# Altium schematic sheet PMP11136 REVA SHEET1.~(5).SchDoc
size 431 x 279 mm; Date: Not shown in title block; ApprovedBy: Not shown in title block; CheckedBy: Not shown in title block; Author: Not shown in title block; CompanyName: Not shown in title block; Engineer: Not shown in title block; Organization: Not shown in title block; Address1: Not shown in title block; Address2: Not shown in title block; Address3: Not shown in title block; Address4: Not shown in title block; DocumentNumber: 1; Revision: Use project parameter SCH_Rev; SheetNumber: 1; SheetTotal: 3; PageSetup: Record=PageOptions¦CenterHorizontal=True¦CenterVertical=True¦PrintScale=1.00¦XCorrection=1.00¦YCorrection=1.00¦PrintKind=0¦BorderSize=5000000¦LeftOffset=0¦BottomOffset=0¦Orientation=2¦PaperLength=1000¦PaperWidth=1000¦Scale=100¦PaperSource=15¦PrintQuality=600¦MediaType=1¦DitherType=10¦PaperKind=Letter¦PrintScaleMode=1
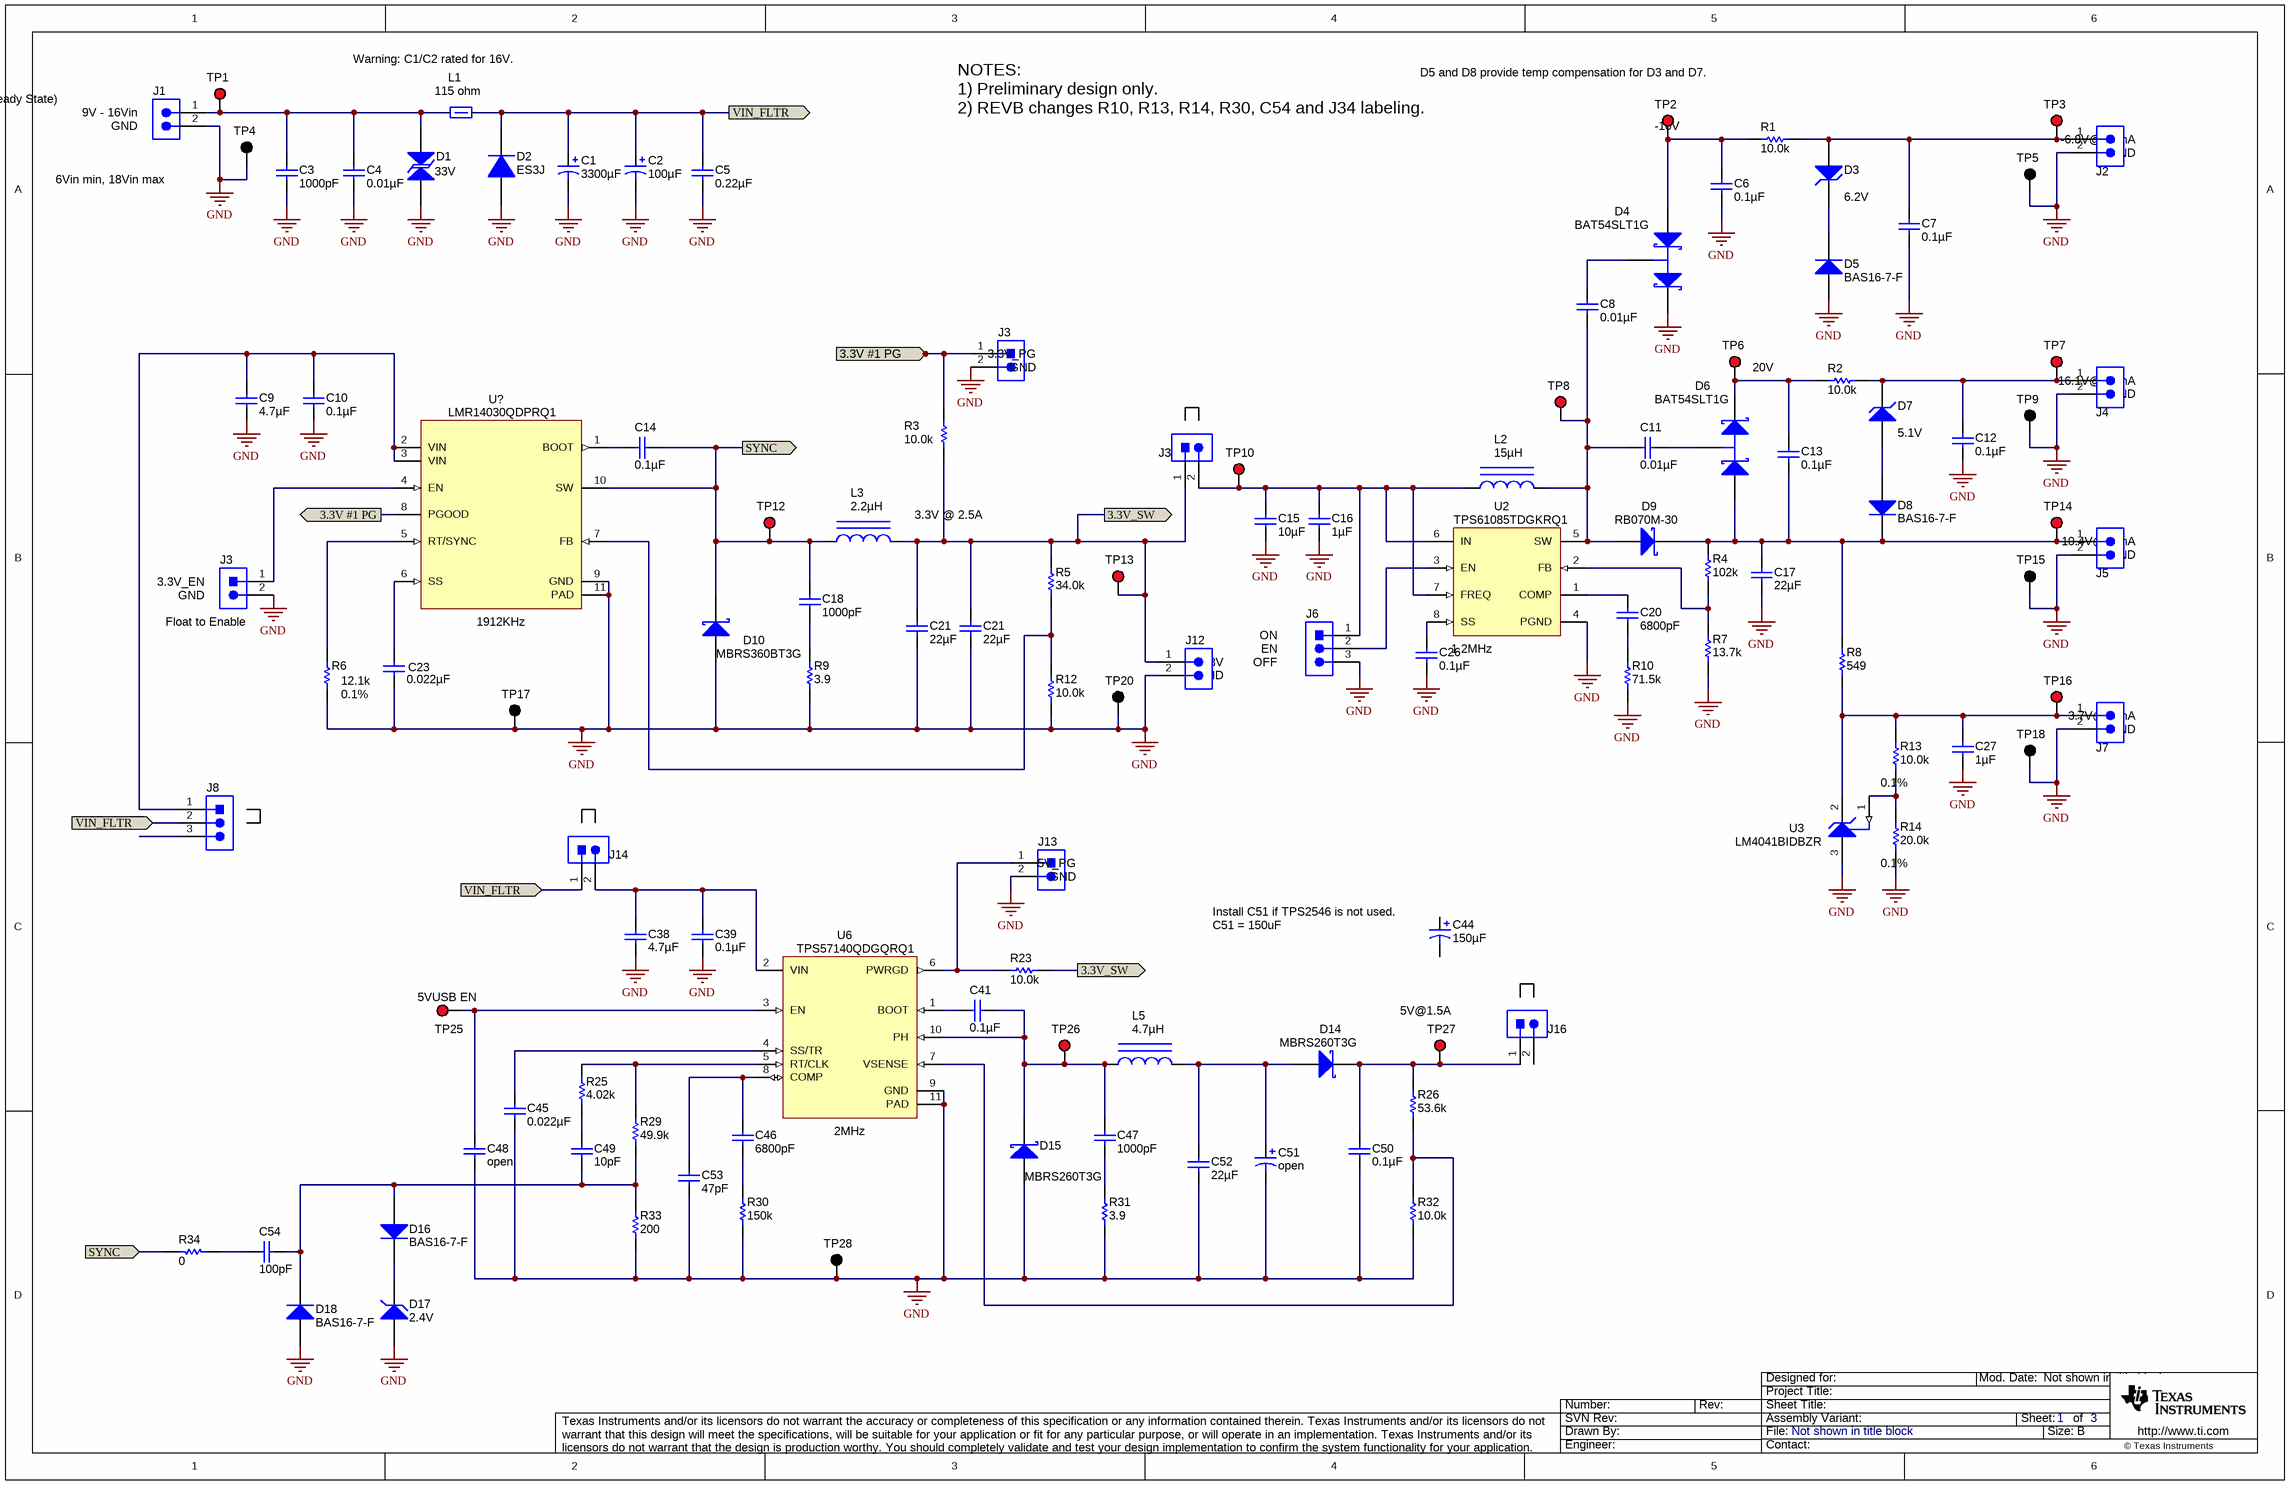
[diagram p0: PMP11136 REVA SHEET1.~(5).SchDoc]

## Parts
(Parts that share a designator on the sheet are numbered #1, #2 ... from top to bottom, then left to right.)
C1  ValueDisplayed: 3300µF  [SM_RADIAL_J16]  (hidden comment: EEV-FK1C332M)
C2  ValueDisplayed: 100µF  [SM_RADIAL_D]  (hidden comment: EEE-FK1C101P)
C3  ValueDisplayed: 1000pF  [0603]  (hidden comment: C1608C0G2A102J)
C4  ValueDisplayed: 0.01µF  [0603]  (hidden comment: C1608X7R2A103K)
C5  ValueDisplayed: 0.22µF  [0603]  (hidden comment: C1608X7R1H224K080AB)
C6  ValueDisplayed: 0.1µF  [0603]  (hidden comment: C1608X7R1H104K)
C7  ValueDisplayed: 0.1µF  [0603]  (hidden comment: C1608X7R1H104K)
C8  ValueDisplayed: 0.01µF  [0603]  (hidden comment: C1608X7R1H103K)
C9  ValueDisplayed: 4.7µF  [1210]  (hidden comment: C3225X7R1H475M250AB)
C10  ValueDisplayed: 0.1µF  [0603]  (hidden comment: C1608X7R1H104K)
C11  ValueDisplayed: 0.01µF  [0603]  (hidden comment: C1608X7R1H103K)
C12  ValueDisplayed: 0.1µF  [0603]  (hidden comment: C1608X7R1H104K)
C13  ValueDisplayed: 0.1µF  [0603]  (hidden comment: C1608X7R1H104K)
C14  ValueDisplayed: 0.1µF  [0603]  (hidden comment: C1608X7R1H104K)
C15  ValueDisplayed: 10µF  [0805]  (hidden comment: GRM21BR71A106KE51L)
C16  ValueDisplayed: 1µF  [0603]  (hidden comment: C1608X7R1E105K)
C17  ValueDisplayed: 22µF  [1210]  (hidden comment: C3225X7R1A226M230AC)
C18  ValueDisplayed: 1000pF  [0603]  (hidden comment: C1608C0G2A102J)
C20  ValueDisplayed: 6800pF  [0603]  (hidden comment: C1608C0G1E682J)
C21#1  ValueDisplayed: 22µF  [1210]  (hidden comment: C3225X7R1C226M250AC)
C21#2  ValueDisplayed: 22µF  [1210]  (hidden comment: C3225X7R1C226M250AC)
C23  ValueDisplayed: 0.022µF  [0603]  (hidden comment: C1608X7R1H223K)
C26  ValueDisplayed: 0.1µF  [0603]  (hidden comment: C1608X7R1H104K)
C27  ValueDisplayed: 1µF  [0603]  (hidden comment: C1608X7R1E105K)
C38  ValueDisplayed: 4.7µF  [1210]  (hidden comment: C3225X7R1H475M250AB)
C39  ValueDisplayed: 0.1µF  [0603]  (hidden comment: C1608X7R1H104K)
C41  ValueDisplayed: 0.1µF  [0603]  (hidden comment: C1608X7R1H104K)
C44  ValueDisplayed: 150µF  [TPB_D4]  (hidden comment: 10TPB150ML)
C45  ValueDisplayed: 0.022µF  [0603]  (hidden comment: C1608X7R1H223K)
C46  ValueDisplayed: 6800pF  [0603]  (hidden comment: C1608C0G1E682J)
C47  ValueDisplayed: 1000pF  [0603]  (hidden comment: C1608C0G2A102J)
C48  ValueDisplayed: open  [0603]
C49  ValueDisplayed: 10pF  [0603]  (hidden comment: C1608C0G1H100D)
C50  ValueDisplayed: 0.1µF  [0603]  (hidden comment: C1608X7R1H104K)
C51  ValueDisplayed: open  [TPB_D4]
C52  ValueDisplayed: 22µF  [1210]  (hidden comment: C3225X7R1A226M230AC)
C53  ValueDisplayed: 47pF  [0603]  (hidden comment: C1608C0G1H470J)
C54  ValueDisplayed: 100pF  [0603]  (hidden comment: C1608C0G1H101J)
D1  value 33V  [DO-214AB-Bi]  (hidden comment: 1.5SMC33CA-E3/57T)
D2  ES3J  [SMC]
D3  value 6.2V  [SOD-123]  (hidden comment: MMSZ5234B-7-F)
D4  BAT54SLT1G  [SOT-23]
D5  BAS16-7-F  [SOT-23]
D6  BAT54SLT1G  [SOT-23]
D7  value 5.1V  [SOD-123]  (hidden comment: MMSZ5231B-7-F)
D8  BAS16-7-F  [SOT-23]
D9  RB070M-30  [SOD-123]
D10  MBRS360BT3G  [SMB]
D14  MBRS260T3G  [SMB]
D15  MBRS260T3G  [SMB]
D16  BAS16-7-F  [SOT-23]
D17  value 2.4V  [SOD-123]  (hidden comment: MMSZ5221B-7-F)
D18  BAS16-7-F  [SOT-23]
J1  ED555/2DS  [TERM_BLK_ED555-2DS]  (value not drawn)
J2  ED555/2DS  [TERM_BLK_ED555-2DS]  (value not drawn)
J3#1  PEC02SAAN  [CONN_PEC02SAAN]  (value not drawn)
J3#2  PEC02SAAN  [CONN_PEC02SAAN]  (value not drawn)
J3#3  PEC02SAAN  [CONN_PEC02SAAN]  (value not drawn)
J4  ED555/2DS  [TERM_BLK_ED555-2DS]  (value not drawn)
J5  ED555/2DS  [TERM_BLK_ED555-2DS]  (value not drawn)
J6  PEC03SAAN  [CONN_PEC03SAAN]  (value not drawn)
J7  ED555/2DS  [TERM_BLK_ED555-2DS]  (value not drawn)
J8  PEC03SAAN  [CONN_PEC03SAAN]  (value not drawn)
J12  ED555/2DS  [TERM_BLK_ED555-2DS]  (value not drawn)
J13  PEC02SAAN  [CONN_PEC02SAAN]  (value not drawn)
J14  PEC02SAAN  [CONN_PEC02SAAN]  (value not drawn)
J16  PEC02SAAN  [CONN_PEC02SAAN]  (value not drawn)
L1  value 115 ohm  [28F0181]  (hidden comment: 28F0181-1SR-10)
L2  ValueDisplayed: 15µH  [IND_VLF403215]  (hidden comment: VLF403215MT- 150M)
L3  ValueDisplayed: 2.2µH  [SDR7045]  (hidden comment: SLF6045T-2R2N3R3-3PF)
L5  ValueDisplayed: 4.7µH  [SDR7045]  (hidden comment: SLF6045T-4R7N2R4-3PF)
R1  ValueDisplayed: 10.0k  [0603]  (hidden comment: CRCW060310K0FKEA)
R2  ValueDisplayed: 10.0k  [0603]  (hidden comment: CRCW060310K0FKEA)
R3  ValueDisplayed: 10.0k  [0603]  (hidden comment: CRCW060310K0FKEA)
R4  ValueDisplayed: 102k  [0603]  (hidden comment: CRCW0603102KFKEA)
R5  ValueDisplayed: 34.0k  [0603]  (hidden comment: CRCW060334K0FKEA)
R6  Value1: 0.1%  ValueDisplayed: 12.1k  [0603]
R7  ValueDisplayed: 13.7k  [0603]  (hidden comment: CRCW060313K7FKEA)
R8  value 549  [0805_HV]  (hidden comment: CRCW0805549RFKEA)
R9  value 3.9  [2010]  (hidden comment: CRCW20103R90JNEF)
R10  ValueDisplayed: 71.5k  [0603]  (hidden comment: CRCW060371K5FKEA)
R12  ValueDisplayed: 10.0k  [0603]  (hidden comment: CRCW060310K0FKEA)
R13  ValueDisplayed: 10.0k  [0603]  (hidden comment: CRCW060310K0FKEA)
R14  ValueDisplayed: 20.0k  [0603]  (hidden comment: CRCW0603210K0FKEA)
R23  ValueDisplayed: 10.0k  [0603]  (hidden comment: CRCW060310K0FKEA)
R25  ValueDisplayed: 4.02k  [0603]  (hidden comment: CRCW06034K02FKEA)
R26  ValueDisplayed: 53.6k  [0603]  (hidden comment: CRCW060353K6FKEA)
R29  ValueDisplayed: 49.9k  [0603]  (hidden comment: CRCW060349K9FKEA)
R30  ValueDisplayed: 150k  [0603]  (hidden comment: CRCW0603150KFKEA)
R31  value 3.9  [2010]  (hidden comment: CRCW20103R90JNEF)
R32  ValueDisplayed: 10.0k  [0603]  (hidden comment: CRCW060310K0FKEA)
R33  ValueDisplayed: 200  [0603]  (hidden comment: CRCW0603200RFKEA)
R34  ValueDisplayed: 0  [0603]  (hidden comment: CRCW06030000Z0EA)
TP1  5000  [Keystone5000]  (value not drawn)
TP2  5000  [Keystone5000]  (value not drawn)
TP3  5000  [Keystone5000]  (value not drawn)
TP4  5001  [Keystone5001]  (value not drawn)
TP5  5001  [Keystone5001]  (value not drawn)
TP6  5000  [Keystone5000]  (value not drawn)
TP7  5000  [Keystone5000]  (value not drawn)
TP8  5000  [Keystone5000]  (value not drawn)
TP9  5001  [Keystone5001]  (value not drawn)
TP10  5000  [Keystone5000]  (value not drawn)
TP12  5000  [Keystone5000]  (value not drawn)
TP13  5000  [Keystone5000]  (value not drawn)
TP14  5000  [Keystone5000]  (value not drawn)
TP15  5001  [Keystone5001]  (value not drawn)
TP16  5000  [Keystone5000]  (value not drawn)
TP17  5001  [Keystone5001]  (value not drawn)
TP18  5001  [Keystone5001]  (value not drawn)
TP20  5001  [Keystone5001]  (value not drawn)
TP25  5000  [Keystone5000]  (value not drawn)
TP26  5000  [Keystone5000]  (value not drawn)
TP27  5000  [Keystone5000]  (value not drawn)
TP28  5001  [Keystone5001]  (value not drawn)
U2  TPS61085TDGKRQ1  [DGK0008A_N]
U3  LM4041BIDBZR  [DBZ0003A_N]
U6  TPS57140QDGQRQ1  [DGQ0010D_N]
U?  LMR14030QDPRQ1  [DPR0010A]

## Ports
3.3V #1 PG, 3.3V_SW, SYNC, VIN_FLTR

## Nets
GND: C1.2(-) C2.2(-) C3.2 C4.2 C5.2 C6.2 C7.2 C9.1 C10.2 C12.2 C15.2 C16.2 C17.2 C21#1.2 C21#2.2 C23.2 C26.2 C27.2 C38.1 C39.2 C45.2 C48.2 C50.2 C51.2(-) C52.2 C53.2 D1.1 D2.2(A) D4.2(K) D5.1(A) D10.2(A) D15.2(A) D17.2(A) D18.1(A) J1.2 J2.2 J3#1.2 J3#3.2 J4.2 J5.2 J6.3 J7.2 J12.2 J13.2 R6.1 R7.1 R9.1 R10.1 R12.1 R14.1 R30.1 R31.1 R32.1 R33.1 TP4.1 TP5.1 TP9.1 TP15.1 TP17.1 TP18.1 TP20.1 TP28.1 U2.4(PGND) U3.3(ANODE) U6.9(GND) U6.11(PAD) U?.9(GND) U?.11(PAD)
3.3V #1 PG: J3#1.1 R3.2 U?.8(PGOOD) ; port 3.3V #1 PG
3.3V_SW: C21#1.1 C21#2.1 J3#2.1 J12.1 L3.2 R3.1 R5.2 R23.1 TP13.1 ; port 3.3V_SW
SYNC: C14.2 C18.1 D10.1(K) L3.1 R34.1 TP12.1 U?.10(SW) ; port SYNC
VIN_FLTR: C1.1(+) C2.1(+) C5.1 D2.1(K) J8.2 J14.1 L1.2 ; port VIN_FLTR
NetC3_1: C3.1 C4.1 D1.2 J1.1 L1.1 TP1.1
NetC6_1: C6.1 D4.1(A) R1.2 TP2.1
NetC7_1: C7.1 D3.2(A) J2.1 R1.1 TP3.1
NetC8_1: C8.1 C11.1 D9.2(A) L2.2 TP8.1 U2.5(SW)
NetC8_2: C8.2 D4.3(C)
NetC9_2: C9.2 C10.1 J8.1 U?.2(VIN) U?.3(VIN)
NetC11_2: C11.2 D6.3(C)
NetC12_1: C12.1 D7.1(K) J4.1 R2.1 TP7.1
NetC13_1: C13.1 D6.2(K) R2.2 TP6.1
NetC13_2: C13.2 C17.1 D6.1(A) D8.3(K) D9.1(K) J5.1 R4.2 R8.2 TP14.1
NetC14_1: C14.1 U?.1(BOOT)
NetC15_1: C15.1 C16.1 J3#2.2 J6.1 L2.1 TP10.1 U2.6(IN) U2.7(FREQ)
NetC18_2: C18.2 R9.2
NetC20_1: C20.1 U2.1(COMP)
NetC20_2: C20.2 R10.2
NetC23_1: C23.1 U?.6(SS)
NetC26_1: C26.1 U2.8(SS)
NetC27_1: C27.1 J7.1 R8.1 R13.2 TP16.1 U3.2(CATHODE)
NetC38_2: C38.2 C39.1 J14.2 U6.2(VIN)
NetC41_1: C41.1 U6.1(BOOT)
NetC41_2: C41.2 C47.1 D15.1(K) L5.1 TP26.1 U6.10(PH)
NetC45_1: C45.1 U6.4(SS/TR)
NetC46_1: C46.1 C53.1 U6.8(COMP)
NetC46_2: C46.2 R30.2
NetC47_2: C47.2 R31.2
NetC48_1: C48.1 TP25.1 U6.3(EN)
NetC49_1: C49.1 R25.2
NetC49_2: C49.2 C54.1 D16.1(A) D18.3(K) R29.1 R33.2
NetC50_1: C50.1 D14.1(K) J16.1 R26.2 TP27.1
NetC51_1: C51.1(+) C52.1 D14.2(A) L5.2
NetC54_2: C54.2 R34.2
NetD3_1: D3.1(K) D5.3(K)
NetD7_2: D7.2(A) D8.1(A)
NetD16_3: D16.3(K) D17.1(K)
NetJ3#3_1: J3#3.1 U?.4(EN)
NetJ6_2: J6.2 U2.3(EN)
NetJ13_1: J13.1 R23.2 U6.6(PWRGD)
NetR4_1: R4.1 R7.2 U2.2(FB)
NetR5_1: R5.1 R12.2 U?.7(FB)
NetR6_2: R6.2 U?.5(RT/SYNC)
NetR13_1: R13.1 R14.2 U3.1(FB)
NetR25_1: R25.1 R29.2 U6.5(RT/CLK)
NetR26_1: R26.1 R32.2 U6.7(VSENSE)

Not connected (* = marked no-connect by the designer): C44 1(+) 2(-); J8 3; J16 2

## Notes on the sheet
- (near J1) (Steady State)
- Warning: C1/C2 rated for 16V.
- D5 and D8 provide temp compensation for D3 and D7.
- (near J1) 9V - 16Vin
- (near J1) GND
- NOTES:
  1) Preliminary design only.
  2) REVB changes R10, R13, R14, R30, C54 and J34 labeling.
- (near TP2) -10V
- (near J2) -6.8V@0.3mA
- (near J2) GND
- (near J1) 6Vin min, 18Vin max
- (near J3#1) 3.3V_PG
- (near J3#1) GND
- 20V
- (near J4) 16.1V@0.3mA
- (near J4) GND
- 3.3V @ 2.5A
- (near J5) 10.4V@30mA
- (near J5) GND
- (near J3#3) 3.3V_EN
- (near J3#3) GND
- (near J3#3) Float to Enable
- (near U?) 1912KHz
- (near J6) ON
- (near J12) 3.3V
- (near J12) GND
- (near J6) EN
- (near J6) OFF
- (near U2) 1.2MHz
- (near J7) 3.7V@10mA
- (near J7) GND
- (near R13) 0.1%
- (near J13) 5V_PG
- (near J13) GND
- (near R14) 0.1%
- (near C44) Install C51 if TPS2546 is not used.
  C51 = 150uF
- (near TP25) 5VUSB EN
- (near TP27) 5V@1.5A
- (near U6) 2MHz

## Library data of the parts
C1 = EEV-FK1C332M: CAP, AL, 3300 µF, 16 V, +/- 20%, 0.035 ohm, SMD; Manufacturer: Panasonic; Polarized: Y; CompType: Capacitor; Value: 3300uF; U/M: EA; Cap_F: 0.0033; Tolerance_%: 20; VDC_V: 16; Value2: 16V; ESR_ohm: 0.035; IRMS_A: 1.8; TaMin_C: -55; TaMax_C: 105; Cap_Case: J16
C2 = EEE-FK1C101P: CAP, AL, 100 µF, 16 V, +/- 20%, 0.36 ohm, SMD; Manufacturer: Panasonic; Polarized: Y; CompType: Capacitor; Value: 100uF; U/M: EA; Cap_F: 0.0001; Tolerance_%: 20; VDC_V: 16; Value2: 16V; ESR_ohm: 0.36; IRMS_A: 0.24; TaMin_C: -55; TaMax_C: 105; Cap_Case: D
C3 C18 C47 = C1608C0G2A102J: CAP, CERM, 1000 pF, 100 V, +/- 5%, C0G/NP0, 0603; Manufacturer: TDK; Polarized: N; CompType: Capacitor; Value: 1000pF; U/M: EA; Cap_F: 0.000000001; Tolerance_%: 5; ESR_ohm: 0.0589; Value1: 0.0589 ohm; VDC_V: 100; Value2: 100V; TaMin_C: -55; TaMax_C: 125
C4 = C1608X7R2A103K: CAP, CERM, 0.01 µF, 100 V, +/- 10%, X7R, 0603; Manufacturer: TDK; Polarized: N; CompType: Capacitor; Value: 0.01uF; U/M: EA; Cap_F: 0.00000001; Tolerance_%: 10; ESR_ohm: 0.0661; Value1: 0.0661 ohm; VDC_V: 100; Value2: 100V; TaMin_C: -55; TaMax_C: 125
C5 = C1608X7R1H224K080AB: CAP, CERM, 0.22 µF, 50 V, +/- 10%, X7R, 0603; Manufacturer: TDK; Polarized: N; CompType: Capacitor; Value: 0.22uF; U/M: EA; Cap_F: 0.00000022; Tolerance_%: 10; Value1: Unknown; VDC_V: 50; Value2: 50V; TaMin_C: -55; TaMax_C: 125
C6 C7 C10 C12-C14 C26 C39 C41 C50 = C1608X7R1H104K: CAP, CERM, 0.1uF, 50V, +/-10%, X7R, 0603; Manufacturer: TDK; Polarized: N; CompType: Capacitor; U/M: EA; Cap_F: 0.0000001; Tolerance_%: 10; ESR_Ohm: 0.017; Value1: 0.017 ohm; VDC_V: 50; TaMin_C: -55; TaMax_C: 125
C8 C11 = C1608X7R1H103K: CAP, CERM, 0.01 µF, 50 V, +/- 10%, X7R, 0603; Manufacturer: TDK; Polarized: N; CompType: Capacitor; Value: 0.01uF; U/M: EA; Cap_F: 0.00000001; Tolerance_%: 10; ESR_ohm: 0.0539; Value1: 0.0539 ohm; VDC_V: 50; Value2: 50V; TaMin_C: -55; TaMax_C: 125
C9 C38 = C3225X7R1E106M: CAP, CERM, 4.7uF, 50V, +/-20%, X7R, 1210; Manufacturer: TDK; Polarized: N; CompType: Capacitor; U/M: EA; Cap_F: 0.00001; Tolerance_%: 20; ESR_Ohm: 0.0027; Value1: 0.0027 ohm; VDC_V: 50; IRMS_A: 3; TaMin_C: -55; TaMax_C: 125
C15 = GRM21BR71A106KE51L: CAP, CERM, 10uF, 10V, +/-10%, X7R, 0805; Manufacturer: MuRata; Polarized: N; CompType: Capacitor; U/M: EA; Cap_F: 0.00001; Tolerance_%: 10; ESR_Ohm: 0.003; Value1: 0.003 ohm; TaMin_C: -55; TaMax_C: 125
C16 C27 = C1608X7R1C105K: CAP, CERM, 1uF, 25V, +/-10%, X7R, 0603; Manufacturer: TDK; Polarized: N; CompType: Capacitor; U/M: EA; Cap_F: 0.000001; Tolerance_%: 10; ESR_Ohm: 0.0057; Value1: 0.0057 ohm; VDC_V: 25; TaMin_C: -55; TaMax_C: 125
C17 C21#1 C21#2 C52 = C3225X7R1C226M: CAP, CERM, 22 µF, 16 V, +/- 20%, X7R, 1210; Manufacturer: TDK; Polarized: N; CompType: Capacitor; Value: 22uF; U/M: EA; Cap_F: 0.000022; Tolerance_%: 20; ESR_ohm: 0.002; Value1: 0.002 ohm; VDC_V: 16; Value2: 16V; IRMS_A: 8.11; TaMin_C: -55; TaMax_C: 125
C20 C46 = C1608C0G1E682J: CAP, CERM, 6800 pF, 25 V, +/- 5%, C0G/NP0, 0603; Manufacturer: TDK; Polarized: N; CompType: Capacitor; Value: 6800pF; U/M: EA; Cap_F: 0.0000000068; Tolerance_%: 5; Value1: Unknown; VDC_V: 25; Value2: 25V; TaMin_C: -55; TaMax_C: 125
C23 C45 = C1608X7R1H223K: CAP, CERM, 0.022 µF, 50 V, +/- 10%, X7R, 0603; Manufacturer: TDK; Polarized: N; CompType: Capacitor; Value: 0.022uF; U/M: EA; Cap_F: 0.000000022; Tolerance_%: 10; ESR_ohm: 0.0383; Value1: 0.0383 ohm; VDC_V: 50; Value2: 50V; TaMin_C: -55; TaMax_C: 125
C44 = 10TPB220M: CAP, 150uF, 10V, +/-20%, 0.04 ohm, SMD; Manufacturer: Panasonic; Polarized: Y; CompType: Capacitor; U/M: EA; Cap_F: 0.00022; Tolerance_%: 20; VDC_V: 10; ESR_Ohm: 0.04; IRMS_A: 3; TaMin_C: -55; TaMax_C: 105; Cap_Case: D
C48 = C1608C0G1H102J: CAP, CERM, open, 0603; Polarized: N; CompType: Capacitor; U/M: EA; Cap_F: 0.000000001; Tolerance_%: 5; ESR_ohm: 0.0563; TempCo: C0G/NP0; TaMin_C: -55; TaMax_C: 125
C49 = C1608C0G1H100D: CAP, CERM, 10 pF, 50 V, +/- 5%, C0G/NP0, 0603; Manufacturer: TDK; Polarized: N; CompType: Capacitor; Value: 10pF; U/M: EA; Cap_F: 0.00000000001; Tolerance_%: 5; ESR_ohm: 0.3492; Value1: 0.3492 ohm; VDC_V: 50; Value2: 50V; TaMin_C: -55; TaMax_C: 125
C51 = 10TPB220M: CAP, open, SMD; Polarized: Y; CompType: Capacitor; U/M: EA; Cap_F: 0.00022; Tolerance_%: 20; ESR_Ohm: 0.04; IRMS_A: 3; TaMin_C: -55; TaMax_C: 105; Cap_Case: D
C53 = C1608C0G1H470J: CAP, CERM, 47 pF, 50 V, +/- 5%, C0G/NP0, 0603; Manufacturer: TDK; Polarized: N; CompType: Capacitor; Value: 47pF; U/M: EA; Cap_F: 0.000000000047; Tolerance_%: 5; ESR_ohm: 0.22; Value1: 0.22 ohm; VDC_V: 50; Value2: 50V; TaMin_C: -55; TaMax_C: 125
C54 = C1608C0G1H101J: CAP, CERM, 100 pF, 50 V, +/- 5%, C0G/NP0, 0603; Manufacturer: TDK; Polarized: N; CompType: Capacitor; Value: 100pF; U/M: EA; Cap_F: 0.0000000001; Tolerance_%: 5; ESR_ohm: 0.1679; Value1: 0.1679 ohm; VDC_V: 50; Value2: 50V; TaMin_C: -55; TaMax_C: 125
D1 = 1.5SMC33CA-E3/57T: Diode, TVS, Bi, 33V, 1500W, DO-214AB; Manufacturer: Vishay-Dale; U/M: EA; Power_W: 1500; Vr_V: 28.2; RJA_CperW: 75
D2 = ES3D-E3/57T: Diode, Ultrafast, 600V, 3A, SMC; Manufacturer: Fairchild; U/M: EA; Vf_V: 0.9; Value2: 0.9V; Io_A: 3; Vr_V: 600; TJmax_C: 150
D3 = MMSZ5234B-7-F: Diode, Zener, 6.2V, 500 mW, SOD-123; Manufacturer: Diodes Inc.; SymbolCreator: a0412235; U/M: EA; Power_W: 0.5; Vz_V: 6.2; Value1: 0.5W; RJA_CperW: 350
D4 D6 = BAT54SLT1G: Diode, Schottky, 30V, 0.2A, SOT-23; Manufacturer: ON Semiconductor; U/M: EA; Vf_V: 0.8; Value2: 0.8V; Io_A: 0.2; Vr_V: 30; TJmax_C: 150
D5 D8 D16 D18 = BAS16-7-F: Diode, Ultrafast, 75V, 0.3A, SOT-23; Manufacturer: Diodes Inc.; U/M: EA; Vf_V: 1.125; Value2: 1.125V; Io_A: 0.3; Vr_V: 75
D7 = MMSZ5231B-7-F: Diode, Zener, 5.1V, 500 mW, SOD-123; Manufacturer: Diodes Inc.; SymbolCreator: a0412235; U/M: EA; Power_W: 0.5; Vz_V: 5.1; Value1: 0.5W; RJA_CperW: 350
D9 = B130LAW-7-F: Diode, Schottky, 30V, 1.5A, SOD-123; Manufacturer: Rohm; U/M: EA; Vf_V: 0.38; Value1: 1A; Value2: 0.38V; Io_A: 1.5; Vr_V: 30; TJmax_C: 125
D10 = MBRS260T3G: Diode, Schottky, 60V, 3A, SMB; Manufacturer: ON Semiconductor; U/M: EA; Vf_V: 0.63; Value2: 0.63V; Io_A: 2; Vr_V: 60; TJmax_C: 125; RJC_CperW: 24
D14 D15 = MBRS260T3G: Diode, Schottky, 60V, 2A, SMB; Manufacturer: ON Semiconductor; U/M: EA; Vf_V: 0.63; Value2: 0.63V; Io_A: 2; Vr_V: 60; TJmax_C: 125; RJC_CperW: 24
D17 = MMSZ5221B-7-F: Diode, Zener, 2.4V, 500 mW, SOD-123; Manufacturer: Diodes Inc.; SymbolCreator: a0412235; U/M: EA; Power_W: 0.5; Vz_V: 2.4; Value1: 0.5W; RJA_CperW: 350
J1 J2 J4 J5 J7 J12 = ED555/2DS: Terminal Block, 6A, 3.5mm Pitch, 2-Pos, TH; Manufacturer: On-Shore Technology, Inc.; SymbolCreator: a0412235; CompType: Connector; U/M: EA
J3#1-J3#3 J13 J14 J16 = PEC02SAAN: Header, 100mil, 2x1, Tin, TH; Manufacturer: Sullins Connector Solutions; SymbolCreator: a0412235; U/M: EA
J6 J8 = PEC03SAAN: Header, 100mil, 3x1, Tin, TH; Manufacturer: Sullins Connector Solutions; SymbolCreator: a0799628; U/M: EA
L1 = 28F0181-1SR-10: Ferrite Bead, 115 ohm @ 100MHz, 10A, SMD, 2-Leads, Body 8.74x4.65mm; Manufacturer: Laird-Signal Integrity Products; Imax_A: 10; DCR_ohm: 0.001; Value1: 0.001 ohm; ZTyp@100MHz_Ohm: 115
L2 = VLF403215MT- 150M: Inductor, Shielded, Ferrite, 15uH, 0.87A, 0.22 ohm, SMD; Manufacturer: TDK; Ind_H: 15.0E-6; Imax_A: 0.87; Irms: 0.87A @ 40C rise; Isat: 1.19A @ 30% inductance drop; DCR_ohm: 0.22
L3 = SDR7045-2R2M: Inductor, SMT, 3.3A, 18 milliohm; Manufacturer: Bourns; Value: 2.2uH; Ind_H: 2.2E-6; Imax_A: 3.3; DCR_ohm: 0.032; Material: Ferrite
L5 = SDR7045-2R2M: Inductor, SMT, 2.4A, 26.5 milliohm; Manufacturer: Bourns; Value: 4.7uH; Ind_H: 4.7E-6; Imax_A: 2.4; Material: Ferrite
R1-R3 R12 R23 R32 = CRCW060310K0FKEA: RES, 10.0 k, 1%, 0.1 W, 0603; Manufacturer: Vishay-Dale; CompType: Resistor; Value: 10.0k; Res_ohm: 10000; Value_Code: 10k0; Tolerance_%: 1; Power_W: 0.1; Value2: 0.1W; VDC_V: 75; TempCo: 100 ppm/C; EIA_Code: E96; U/M: EA
R4 = CRCW0603102KFKEA: RES, 102 k, 1%, 0.1 W, 0603; Manufacturer: Vishay-Dale; CompType: Resistor; Value: 102k; Res_ohm: 102000; Tolerance_%: 1; Power_W: 0.1; Value2: 0.1W; VDC_V: 75; TempCo: 100 ppm/C; EIA_Code: E96; U/M: EA
R5 = CRCW060334K0FKEA: RES, 34.0 k, 1%, 0.1 W, 0603; Manufacturer: Vishay-Dale; CompType: Resistor; Value: 34.0k; Res_ohm: 34000; Value_Code: 34k0; Tolerance_%: 1; Power_W: 0.1; Value2: 0.1W; VDC_V: 75; TempCo: 100 ppm/C; EIA_Code: E96; U/M: EA
R6 = CRCW060312K1FKEA: RES, 12.1 k, 0.1%, 0.1 W, 0603; Manufacturer: Vishay-Dale; CompType: Resistor; Value: 12.1k; Res_ohm: 12100; Value_Code: 12k1; Tolerance_%: 1; Power_W: 0.1; Value2: 0.1W; VDC_V: 75; TempCo: 100 ppm/C; EIA_Code: E96; U/M: EA
R7 = CRCW060313K7FKEA: RES, 13.7 k, 1%, 0.1 W, 0603; Manufacturer: Vishay-Dale; CompType: Resistor; Value: 13.7k; Res_ohm: 13700; Value_Code: 13k7; Tolerance_%: 1; Power_W: 0.1; Value2: 0.1W; VDC_V: 75; TempCo: 100 ppm/C; EIA_Code: E96; U/M: EA
R8 = CRCW0805549RFKEA: RES, 549 ohm, 1%, 0.125W, 0805; Manufacturer: Vishay-Dale; CompType: Resistor; Value_Code: 549R; Tolerance_%: 1; Power_W: 0.125; VDC_V: 150; TempCo: 100 ppm/C; EIA_Code: E96; U/M: EA
R9 R31 = CRCW20102R70JNEF: RES, 3.9 ohm, 5%, 0.75W, 2010; Manufacturer: Vishay-Dale; CompType: Resistor; Value_Code: 3R90; Tolerance_%: 5; Power_W: 0.75; VDC_V: 400; TempCo: 200 ppm/C; EIA_Code: E24; U/M: EA
R10 = CRCW060371K5FKEA: RES, 71.5 k, 1%, 0.1 W, 0603; Manufacturer: Vishay-Dale; CompType: Resistor; Value: 71.5k; Res_ohm: 71500; Value_Code: 71k5; Tolerance_%: 1; Power_W: 0.1; Value2: 0.1W; VDC_V: 75; TempCo: 100 ppm/C; EIA_Code: E96; U/M: EA
R13 = CRCW060310K0FKEA: RES, 10.0 k, 0.1%, 0.1 W, 0603; Manufacturer: Vishay-Dale; CompType: Resistor; Value: 10.0k; Res_ohm: 10000; Value_Code: 10k0; Tolerance_%: 1; Power_W: 0.1; Value2: 0.1W; VDC_V: 75; TempCo: 100 ppm/C; EIA_Code: E96; U/M: EA
R14 = CRCW060310K0FKEA: RES, 20.0 k, 0.1%, 0.1 W, 0603; Manufacturer: Vishay-Dale; CompType: Resistor; Value: 10.0k; Res_ohm: 10000; Value_Code: 10k0; Tolerance_%: 1; Power_W: 0.1; Value2: 0.1W; VDC_V: 75; TempCo: 100 ppm/C; EIA_Code: E96; U/M: EA
R25 = CRCW06034K02FKEA: RES, 4.02 k, 1%, 0.1 W, 0603; Manufacturer: Vishay-Dale; CompType: Resistor; Value: 4.02k; Res_ohm: 4020; Value_Code: 4k02; Tolerance_%: 1; Power_W: 0.1; Value2: 0.1W; VDC_V: 75; TempCo: 100 ppm/C; EIA_Code: E96; U/M: EA
R26 = CRCW060353K6FKEA: RES, 53.6 k, 1%, 0.1 W, 0603; Manufacturer: Vishay-Dale; CompType: Resistor; Value: 53.6k; Res_ohm: 53600; Value_Code: 53k6; Tolerance_%: 1; Power_W: 0.1; Value2: 0.1W; VDC_V: 75; TempCo: 100 ppm/C; EIA_Code: E96; U/M: EA
R29 = CRCW060349K9FKEA: RES, 49.9 k, 1%, 0.1 W, 0603; Manufacturer: Vishay-Dale; CompType: Resistor; Value: 49.9k; Res_ohm: 49900; Value_Code: 49k9; Tolerance_%: 1; Power_W: 0.1; Value2: 0.1W; VDC_V: 75; TempCo: 100 ppm/C; EIA_Code: E96; U/M: EA
R30 = CRCW0603150KFKEA: RES, 150 k, 1%, 0.1 W, 0603; Manufacturer: Vishay-Dale; CompType: Resistor; Value: 150k; Res_ohm: 150000; Tolerance_%: 1; Power_W: 0.1; Value2: 0.1W; VDC_V: 75; TempCo: 100 ppm/C; EIA_Code: E96; U/M: EA
R33 = CRCW0603200RFKEA: RES, 200, 1%, 0.1 W, 0603; Manufacturer: Vishay-Dale; CompType: Resistor; Value: 200; Value_Code: 200R; Tolerance_%: 1; Power_W: 0.1; Value2: 0.1W; VDC_V: 75; TempCo: 100 ppm/C; EIA_Code: E96; U/M: EA
R34 = CRCW06030000Z0EA: RES, 0, 5%, 0.1 W, 0603; Manufacturer: Vishay-Dale; CompType: Resistor; Value: 0; Value_Code: 0000; Tolerance_%: 5; Power_W: 0.1; Value2: 0.1W; VDC_V: 75; TempCo: 200 ppm/C; EIA_Code: E24; U/M: EA
TP1-TP3 TP6-TP8 TP10 TP12-TP14 TP16 TP25-TP27 = 5000: Test Point, TH, Miniature, Red; Manufacturer: Keystone; CompType: Test Point Loop; U/M: EA
TP4 TP5 TP9 TP15 TP17 TP18 TP20 TP28 = 5001: Test Point, TH, Miniature, Black; Manufacturer: Keystone; CompType: Test Point Loop; U/M: EA
U2 = TPS61085TDGKRQ1: Automotive Catalog 18.5 V, 2 A, 650 KHz / 1.2 MHz Step-Up DC-DC Converter with Forced PWM Mode, 2.3 to 6 V, -40 to 105 degC, 8-pin SOP (DGK8), Green (RoHS & no Sb/Br); Manufacturer: Texas Instruments; Alternate Manufacturer: None; Alternate PartNumber: Equivalent; Iout(Max)(A): 2; Iq(Typ)(mA): 0.07; SubFamily: White LED Driver; Switching Frequency(Max)(kHz): 1500; Topology: Boost; Vin(Max)(V): 6; Vin(Min)(V): 2.3
U3 = LM4041BIDBZR: Adjustable Precision Micropower Shunt Voltage Reference, 0.2% accuracy, 15 ppm / degC, 12 mA, -40 to 85 degC, 3-pin SOT-23 (DBZ), Green (RoHS & no Sb/Br); Manufacturer: Texas Instruments; Alternate Manufacturer: None; Alternate PartNumber: Equivalent; Initial Accuracy @ 25/deg C(%): 0.2; Iout/Iz(Max)(mA): 12; Min Iz for Regulation(uA): 60; Rating: Catalog; Temp Coeff(Max)(ppm/ degree C): 100; Temp Coeff(Typ)(ppm/ degree C): 15; VO Adj(Max)(V): 10; VO Adj(Min)(V): 1.225
U6 = TPS57140QDGQRQ1: 1.5-A 42-V STEP-DOWN SWIFT(TM) DC-DC CONVERTER WITH Eco-mode(TM) CONTROL, DGQ0010D; Alternate Manufacturer: None; Manufacturer: Texas Instruments; SymbolCreator: a0799628; CompType: IC; U/M: EA
U? = LMR14030QDPRQ1: 40V 3.5A SIMPLE SWITCHER® , 2.2MHz Step-Down Regulator with 40μA Quiescent Current, DPR0010A; Manufacturer: Texas Instruments; SymbolCreator: Altium; CompType: IC; U/M: EA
